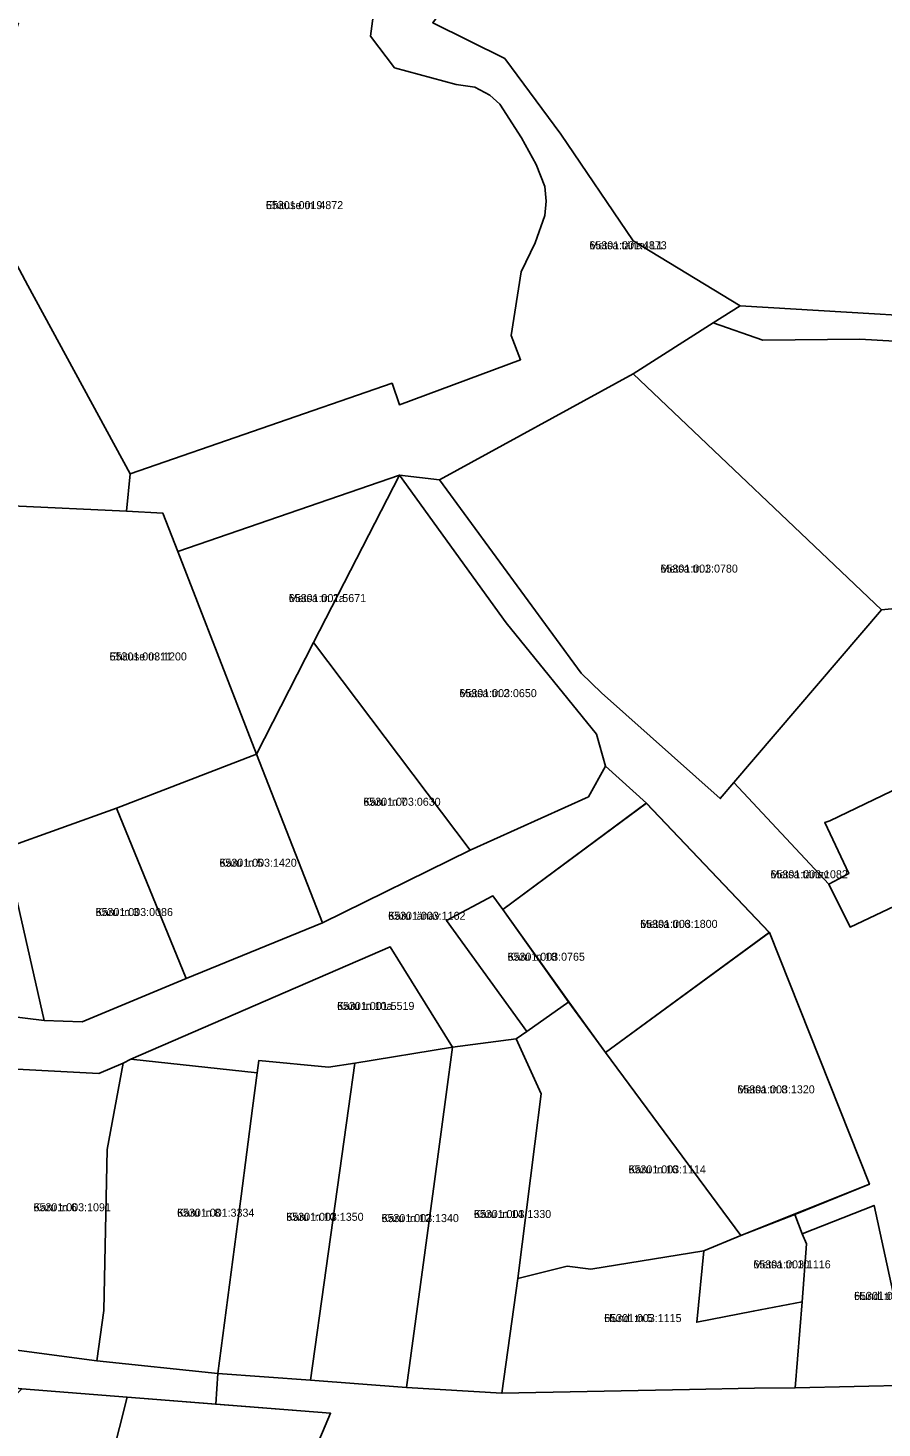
# Model space of a CAD drawing. Extents: x 543236 to 563717, y 6566033 to 6588992.
# Drawn here: x 552283.7 to 552443.9, y 6580060.9 to 6580323.4 of the extents above; entities that cross this region are included whole.
import ezdxf

# ---------------------------------------------------------------- set-up
doc = ezdxf.new("R2010")
doc.units = 0
for name, color, linetype in [('L_AADRESS', 7, 'Continuous'), ('PIIR', 7, 'Continuous'), ('TUNNUS', 7, 'Continuous')]:
    doc.layers.add(name, color=color, linetype=linetype)

msp = doc.modelspace()

# ---------------------------------------------------------------- linework, layer by layer
at = {"layer": 'PIIR'}
for points in [[(552397.21, 6580283.47), (552383.68, 6580303.5), (552373.15, 6580317.65), (552359.63, 6580324.34), (552379.1, 6580351.02), (552386.69, 6580364.61), (552419.98, 6580353.15), (552450.5, 6580401.41), (552417.99, 6580419.18), (552450.88, 6580472.5), (552533.1, 6580467.9), (552535.5, 6580414.15), (552536.36, 6580395), (552489.23, 6580390), (552479.96, 6580389.02), (552479.28, 6580324.8), (552479.14, 6580311), (552471.59, 6580310.81), (552471.9, 6580268.02), (552417.31, 6580271.3)], [(552421.57, 6580264.86), (552412.22, 6580268.11), (552417.31, 6580271.3), (552471.9, 6580268.02), (552493.23, 6580266.92), (552492.91, 6580262.01), (552439.78, 6580265.07)], [(552443.81, 6580214.32), (552397.25, 6580258.55), (552412.22, 6580268.11), (552421.57, 6580264.86), (552439.78, 6580265.07), (552492.91, 6580262.01), (552490.89, 6580218.95), (552479.63, 6580217.82)], [(552443.81, 6580214.32), (552416.15, 6580181.96), (552413.57, 6580178.94), (552391.28, 6580198.72), (552387.46, 6580202.41), (552360.92, 6580238.68), (552397.25, 6580258.55)], [(552337.26, 6580208.18), (552326.59, 6580187.27), (552311.85, 6580225.25), (552353.43, 6580239.55)], [(552337.26, 6580208.18), (552353.43, 6580239.55), (552373.39, 6580211.9), (552390.34, 6580191.02), (552392.05, 6580184.99), (552388.85, 6580179.25), (552366.66, 6580169.23)], [(552280.76, 6580233.83), (552302.21, 6580232.83), (552309, 6580232.44), (552311.85, 6580225.25), (552326.59, 6580187.27), (552300.31, 6580177.12), (552279.41, 6580169.66), (552271.45, 6580166.87), (552277.57, 6580194.38)], [(552443.81, 6580214.32), (552479.63, 6580217.82), (552490.89, 6580218.95), (552490.19, 6580202.83), (552478.73, 6580196.64), (552466.51, 6580190.25), (552463.91, 6580189.04), (552434.13, 6580174.77), (552433.18, 6580174.43), (552437.72, 6580164.89), (552433.95, 6580162.91), (552416.15, 6580181.96)], [(552326.59, 6580187.27), (552337.26, 6580208.18), (552366.66, 6580169.23), (552338.95, 6580155.63)], [(552433.95, 6580162.91), (552437.72, 6580164.89), (552433.18, 6580174.43), (552434.13, 6580174.77), (552463.91, 6580189.04), (552466.51, 6580190.25), (552478.73, 6580196.64), (552490.19, 6580202.83), (552489.64, 6580191.17), (552490.93, 6580188.28), (552473.81, 6580180.34), (552470.01, 6580170), (552437.93, 6580154.83)], [(552300.31, 6580177.12), (552326.59, 6580187.27), (552338.95, 6580155.63), (552313.39, 6580145.17)], [(552229.81, 6580148.06), (552250.46, 6580141.78), (552286.73, 6580137.34), (552293.88, 6580137.05), (552313.39, 6580145.17), (552338.95, 6580155.63), (552366.66, 6580169.23), (552388.85, 6580179.25), (552392.05, 6580184.99), (552399.74, 6580178.05), (552372.77, 6580158.12), (552370.94, 6580160.68), (552362.21, 6580156.09), (552377.28, 6580135.24), (552375.31, 6580133.91), (552363.37, 6580132.31), (552351.67, 6580151.11), (552302.99, 6580130.05), (552301.59, 6580129.34), (552296.98, 6580127.42), (552274.44, 6580128.55), (552247.42, 6580132.19), (552205.05, 6580136.87)], [(552293.88, 6580137.05), (552286.73, 6580137.34), (552279.41, 6580169.66), (552300.31, 6580177.12), (552313.39, 6580145.17)], [(552385.07, 6580140.91), (552372.76, 6580158.12), (552399.7, 6580178.04), (552422.75, 6580153.83), (552392.03, 6580131.34)], [(552286.73, 6580137.34), (552250.46, 6580141.78), (552252.26, 6580157.24), (552265.28, 6580164.71), (552271.45, 6580166.87), (552279.41, 6580169.66)], [(552362.21, 6580156.09), (552370.94, 6580160.68), (552372.77, 6580158.12), (552385.16, 6580140.83), (552377.28, 6580135.24)], [(552422.8, 6580153.85), (552441.55, 6580106.64), (552417.42, 6580097.03), (552392.03, 6580131.34)], [(552363.37, 6580132.31), (552345.05, 6580129.36), (552340.11, 6580128.56), (552327.01, 6580129.8), (552326.7, 6580127.51), (552302.99, 6580130.05), (552351.67, 6580151.11)], [(552375.31, 6580133.91), (552377.28, 6580135.24), (552385.16, 6580140.83), (552392.03, 6580131.34), (552417.42, 6580097.03), (552410.48, 6580094.14), (552389.29, 6580090.7), (552384.87, 6580091.29), (552375.58, 6580088.95), (552378.82, 6580114.24), (552380.01, 6580123.56)], [(552359.96, 6580107.17), (552362.17, 6580123.47), (552363.37, 6580132.31), (552375.31, 6580133.91), (552380.01, 6580123.56), (552378.82, 6580114.24), (552375.58, 6580088.95), (552372.63, 6580067.46), (552354.72, 6580068.56)], [(552345.05, 6580129.36), (552363.37, 6580132.31), (552362.17, 6580123.47), (552359.96, 6580107.17), (552354.72, 6580068.56), (552336.7, 6580069.92), (552342.59, 6580111.89), (552343.85, 6580120.81)], [(552274.44, 6580128.55), (552296.98, 6580127.42), (552301.59, 6580129.34), (552298.56, 6580113.15), (552297.94, 6580082.99), (552296.66, 6580073.52), (552267.93, 6580077.34), (552268.46, 6580081.34), (552268.85, 6580084.31), (552269.35, 6580088.28)], [(552298.56, 6580113.15), (552301.59, 6580129.34), (552302.99, 6580130.05), (552326.7, 6580127.51), (552325.83, 6580120.91), (552323.69, 6580104.38), (552319.3, 6580071.19), (552296.66, 6580073.52), (552297.94, 6580082.99)], [(552336.7, 6580069.92), (552319.3, 6580071.19), (552323.69, 6580104.38), (552325.83, 6580120.91), (552326.7, 6580127.51), (552327.01, 6580129.8), (552340.11, 6580128.56), (552345.05, 6580129.36), (552343.85, 6580120.81), (552342.59, 6580111.89)], [(552428.96, 6580097.32), (552442.42, 6580102.68), (552449.75, 6580068.98), (552427.61, 6580068.46), (552428.92, 6580084.6), (552429.78, 6580095.49)], [(552410.48, 6580094.14), (552417.42, 6580097.03), (552427.54, 6580100.98), (552428.96, 6580097.32), (552429.78, 6580095.49), (552428.92, 6580084.6), (552419.77, 6580082.82), (552409.16, 6580080.76)], [(552375.58, 6580088.95), (552384.87, 6580091.29), (552389.29, 6580090.7), (552410.48, 6580094.14), (552409.16, 6580080.76), (552419.77, 6580082.82), (552428.92, 6580084.6), (552427.61, 6580068.46), (552420.02, 6580068.39), (552407.79, 6580068.19), (552372.63, 6580067.46)], [(552199.82, 6580089.1), (552198.8, 6580093.63), (552241.36, 6580087.86), (552268.85, 6580084.31), (552268.46, 6580081.34), (552267.93, 6580077.34), (552296.66, 6580073.52), (552319.3, 6580071.19), (552318.94, 6580065.41), (552302.33, 6580066.72), (552282.57, 6580068.28), (552202.48, 6580077.23)], [(552319.3, 6580071.19), (552336.7, 6580069.92), (552354.72, 6580068.56), (552372.63, 6580067.46), (552407.79, 6580068.19), (552420.02, 6580068.39), (552427.61, 6580068.46), (552449.75, 6580068.98), (552452.07, 6580052.52), (552399.1, 6580054.96), (552383.52, 6580056.31), (552353.08, 6580053.43), (552345.4, 6580034.96), (552330.54, 6579999.2), (552315.64, 6580004.84), (552340.48, 6580063.71), (552318.94, 6580065.41)], [(552282.57, 6580068.28), (552302.33, 6580066.72), (552288.16, 6580010.84), (552237.03, 6580023.6), (552281.29, 6580067.02)], [(552302.33, 6580066.72), (552340.48, 6580063.71), (552315.64, 6580004.84), (552288.16, 6580010.84)]]:
    msp.add_lwpolyline(points, close=True, dxfattribs=at)
for points in [[(552349.73, 6580335.09), (552347.94, 6580321.84), (552352.5, 6580315.88), (552364.01, 6580312.76), (552367.51, 6580312.26), (552370.38, 6580310.8), (552372.24, 6580309.07), (552376.29, 6580302.8), (552379.06, 6580297.81), (552380.68, 6580293.63), (552380.95, 6580290.94), (552380.67, 6580288.22), (552378.83, 6580283.07), (552376.23, 6580277.67), (552374.34, 6580265.72), (552376.13, 6580261.19), (552353.4, 6580252.76), (552352.01, 6580256.78), (552302.91, 6580239.8), (552283.67, 6580275.08), (552282.1, 6580278.01), (552272.42, 6580295.79), (552281.92, 6580324.33)], [(552359.63, 6580324.34), (552373.15, 6580317.65), (552383.68, 6580303.5), (552397.21, 6580283.47), (552417.31, 6580271.3), (552412.22, 6580268.11), (552397.25, 6580258.55), (552360.92, 6580238.68), (552353.43, 6580239.55), (552311.85, 6580225.25), (552309, 6580232.44), (552302.21, 6580232.83), (552302.91, 6580239.8), (552352.01, 6580256.78), (552353.4, 6580252.76), (552376.13, 6580261.19), (552374.34, 6580265.72), (552376.23, 6580277.67), (552378.83, 6580283.07), (552380.67, 6580288.22), (552380.95, 6580290.94), (552380.68, 6580293.63), (552379.06, 6580297.81), (552376.29, 6580302.8), (552372.24, 6580309.07), (552370.38, 6580310.8), (552367.51, 6580312.26), (552364.01, 6580312.76), (552352.5, 6580315.88), (552347.94, 6580321.84), (552349.73, 6580335.09)], [(552283.67, 6580275.08), (552302.91, 6580239.8), (552302.21, 6580232.83), (552280.76, 6580233.83)], [(552449.75, 6580068.98), (552442.42, 6580102.68), (552428.96, 6580097.32), (552427.54, 6580100.98), (552441.55, 6580106.64), (552422.8, 6580153.85), (552399.74, 6580178.05), (552392.05, 6580184.99), (552390.34, 6580191.02), (552373.39, 6580211.9), (552353.43, 6580239.55), (552360.92, 6580238.68), (552387.46, 6580202.41), (552391.28, 6580198.72), (552413.57, 6580178.94), (552416.15, 6580181.96), (552433.95, 6580162.91), (552437.93, 6580154.83), (552470.01, 6580170)]]:
    msp.add_lwpolyline(points, dxfattribs=at)

# ---------------------------------------------------------------- texts
at = {"layer": 'L_AADRESS'}
for s, p in [('Ehituse tn 9', (552328.34, 6580289.42)), ('Metsa tänav L1', (552389.03, 6580281.9)), ('Metsa tn 1', (552402.37, 6580221.29)), ('Metsa tn 2a', (552332.64, 6580215.76)), ('Ehituse tn 11', (552299.02, 6580204.82)), ('Metsa tn 2', (552364.65, 6580197.94)), ('Karu tn 7', (552346.62, 6580177.58)), ('Karu tn 5', (552319.63, 6580166.15)), ('Metsa tänav', (552423, 6580163.99)), ('Karu tn 3', (552296.4, 6580156.91)), ('Karu tänav', (552351.28, 6580156.21)), ('Metsa tn 6', (552398.57, 6580154.69)), ('Karu tn 18', (552373.68, 6580148.53)), ('Karu tn 10a', (552341.7, 6580139.31)), ('Metsa tn 8', (552416.79, 6580123.67)), ('Karu tn 16', (552396.37, 6580108.67)), ('Karu tn 6', (552284.76, 6580101.57)), ('Karu tn 8', (552311.68, 6580100.55)), ('Karu tn 10', (552332.17, 6580099.78)), ('Karu tn 12', (552350.04, 6580099.54)), ('Karu tn 14', (552367.36, 6580100.31)), ('Metsa tn 10', (552419.79, 6580090.87)), ('Hundi tn 7', (552438.68, 6580084.96)), ('Hundi tn 5', (552391.81, 6580080.8))]:
    msp.add_text(s, height=1.5, dxfattribs=at).set_placement(p)
at = {"layer": 'TUNNUS'}
for s, p in [('65301:001:4872', (552328.34, 6580289.42)), ('65301:001:4873', (552389.03, 6580281.9)), ('65301:003:0780', (552402.37, 6580221.29)), ('65301:001:5671', (552332.64, 6580215.76)), ('65301:003:1200', (552299.02, 6580204.82)), ('65301:003:0650', (552364.65, 6580197.94)), ('65301:003:0630', (552346.62, 6580177.58)), ('65301:003:1420', (552319.63, 6580166.15)), ('65301:003:1082', (552423, 6580163.99)), ('65301:003:0086', (552296.4, 6580156.91)), ('65301:003:1162', (552351.28, 6580156.21)), ('65301:003:1800', (552398.57, 6580154.69)), ('65301:003:0765', (552373.68, 6580148.53)), ('65301:001:5519', (552341.7, 6580139.31)), ('65301:003:1320', (552416.79, 6580123.67)), ('65301:003:1114', (552396.37, 6580108.67)), ('65301:003:1091', (552284.76, 6580101.57)), ('65301:001:3334', (552311.68, 6580100.55)), ('65301:003:1350', (552332.17, 6580099.78)), ('65301:003:1340', (552350.04, 6580099.54)), ('65301:003:1330', (552367.36, 6580100.31)), ('65301:003:1116', (552419.79, 6580090.87)), ('65301:003:1117', (552438.68, 6580084.96)), ('65301:003:1115', (552391.81, 6580080.8))]:
    msp.add_text(s, height=1.5, dxfattribs=at).set_placement(p)

doc.saveas('drawing.dxf')
